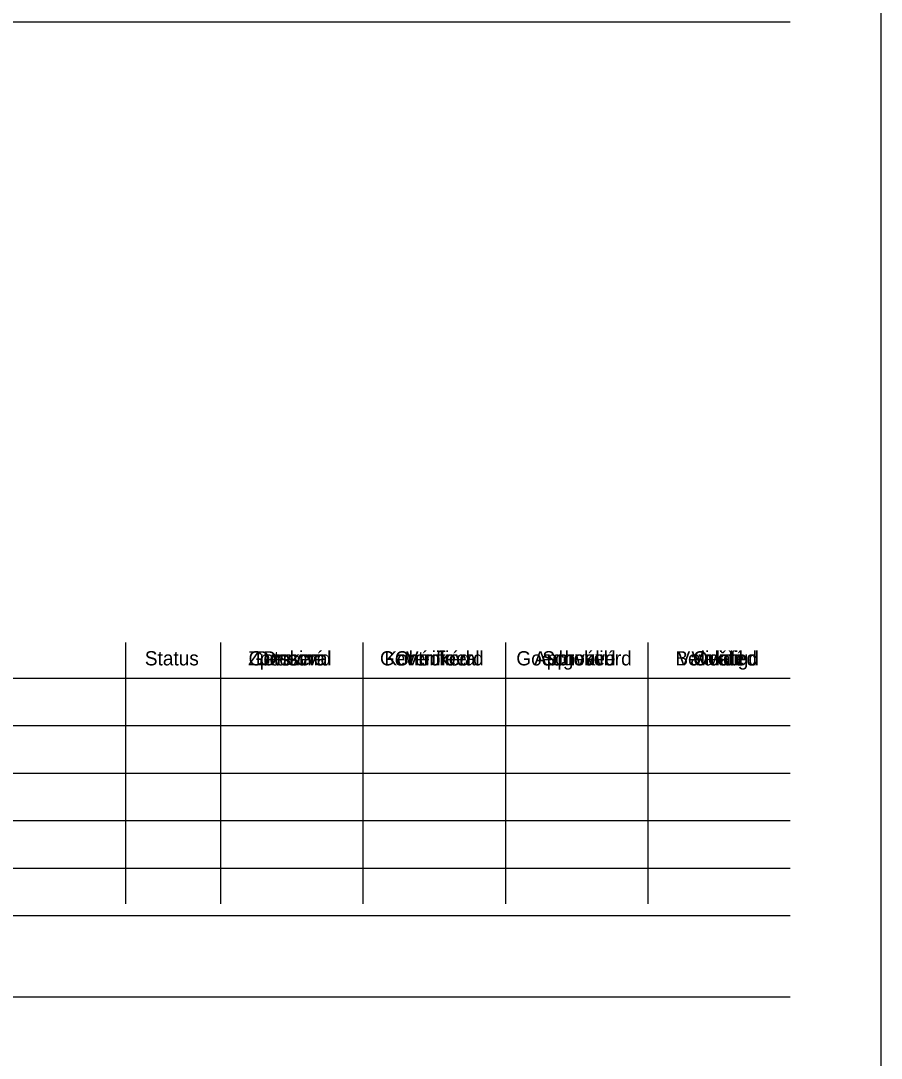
# Model space of a CAD drawing. Extents: x -932963 to -932666, y -737039 to -736000.
# Drawn here: x -932711.7 to -932666.4, y -736983.1 to -736928.5 of the extents above; entities that cross this region are included whole.
import ezdxf

# ---------------------------------------------------------------- set-up
doc = ezdxf.new("R2010")
doc.units = 0
for name, color, linetype in [('Border', 7, 'Continuous'), ('Border_TextCZ', 7, 'Continuous'), ('Border_TextFR', 7, 'Continuous'), ('Border_TextNL', 7, 'Continuous'), ('Border_TextUK', 7, 'Continuous')]:
    doc.layers.add(name, color=color, linetype=linetype)

# ---------------------------------------------------------------- blocks, each defined once
blk = doc.blocks.new('A2_v03_CZ')
at = {"layer": 'Border'}
blk.add_line((0.39358, 0.15206), (0.58358, 0.15206), dxfattribs=at)
blk.add_lwpolyline([(0, 0), (0.594, 0), (0.594, 0.42), (0, 0.42)], close=True, dxfattribs=at)
for points in [[(0.39358, 0.22115), (0.58442, 0.22115)], [(0.51442, 0.15581), (0.51442, 0.12831)], [(0.52442, 0.15581), (0.52442, 0.12831)], [(0.53942, 0.15581), (0.53942, 0.12831)], [(0.55442, 0.15581), (0.55442, 0.12831)], [(0.56942, 0.15581), (0.56942, 0.12831)], [(0.39358, 0.15206), (0.58442, 0.15206)], [(0.39358, 0.14706), (0.58442, 0.14706)], [(0.39358, 0.14206), (0.58442, 0.14206)], [(0.39358, 0.13706), (0.58442, 0.13706)], [(0.39358, 0.13206), (0.58442, 0.13206)], [(0.39358, 0.12706), (0.58442, 0.12706)], [(0.39358, 0.1185), (0.58442, 0.1185)]]:
    blk.add_lwpolyline(points, dxfattribs=at)
at = {"layer": 'Border_TextCZ'}
for s, p in [('Status', (0.51645, 0.1534)), ('Zpracoval', (0.52732, 0.1534)), ('Kontroloval', (0.54168, 0.1534)), ('Schválil', (0.55831, 0.1534)), ('Ověřil', (0.57418, 0.1534))]:
    blk.add_text(s, height=0.0015, dxfattribs=at).set_placement(p)
at = {"layer": 'Border_TextFR'}
for s, p in [('Status', (0.51645, 0.1534)), ('Dessiné', (0.52813, 0.1534)), ('Vérifié', (0.54395, 0.1534)), ('Approuvé', (0.55743, 0.1534)), ('Validé', (0.574, 0.1534))]:
    blk.add_text(s, height=0.0015, dxfattribs=at).set_placement(p)
at = {"layer": 'Border_TextNL'}
for s, p in [('Status', (0.51645, 0.1534)), ('Getekend', (0.52737, 0.1534)), ('Geverifieerd', (0.54121, 0.1534)), ('Goedgekeurd', (0.55557, 0.1534)), ('Bevestigd', (0.57231, 0.1534))]:
    blk.add_text(s, height=0.0015, dxfattribs=at).set_placement(p)
at = {"layer": 'Border_TextUK'}
for s, p in [('Status', (0.51645, 0.1534)), ('Drawn', (0.52889, 0.1534)), ('Checked', (0.54278, 0.1534)), ('Approved', (0.55743, 0.1534)), ('Validated', (0.57255, 0.1534))]:
    blk.add_text(s, height=0.0015, dxfattribs=at).set_placement(p)

msp = doc.modelspace()

# ---------------------------------------------------------------- block references
at = {"layer": 'Border', "xscale": 499.9999999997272, "yscale": 499.9999999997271, "rotation": -4.538738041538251e-11}
msp.add_blockref('A2_v03_CZ', (-932963.362, -737039.103), dxfattribs=at)

doc.saveas('drawing.dxf')
